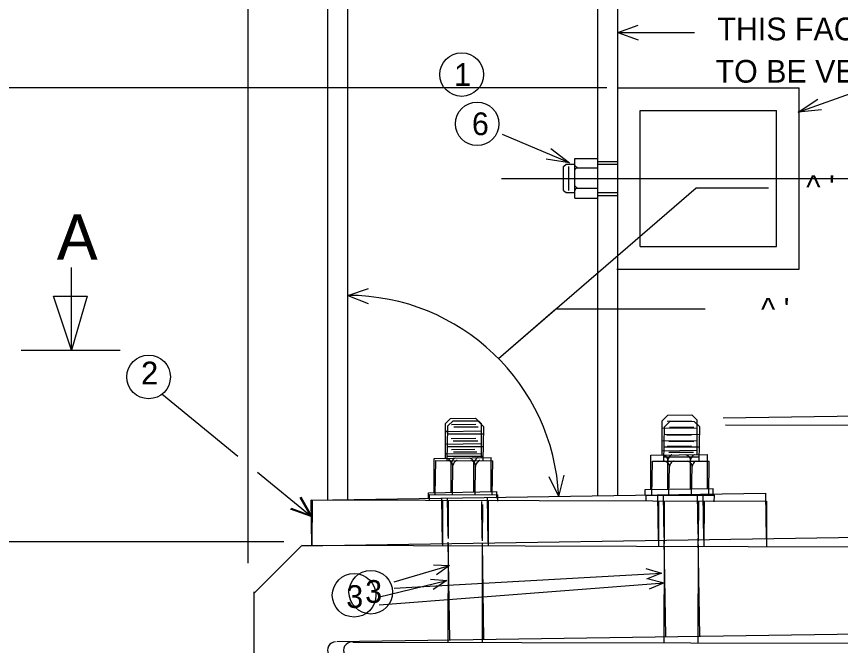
# Model space of a CAD drawing. Extents: x 1509.2 to 1521.3, y 1506 to 1514.6.
# Drawn here: x 1510.447 to 1511.957, y 1509.914 to 1511.069 of the extents above; entities that cross this region are included whole.
import ezdxf

# ---------------------------------------------------------------- set-up
doc = ezdxf.new("R2010")
doc.units = 0
doc.layers.add('Level 3', color=7, linetype='Continuous')
doc.layers.add('Level 4', color=7, linetype='Continuous')

msp = doc.modelspace()

# ---------------------------------------------------------------- linework, layer by layer
at = {"layer": 'Level 3'}
for p, q in [((1511.5127, 1510.1884), (1511.5127, 1512.8863)), ((1511.5491, 1510.1896), (1511.5491, 1512.8862)), ((1511.0178, 1510.1816), (1511.0178, 1512.8483)), ((1511.0543, 1510.1816), (1511.0543, 1512.8483)), ((1510.8717, 1510.0655), (1510.8717, 1511.5101)), ((1511.5491, 1511.0391), (1511.5867, 1511.0528)), ((1511.5491, 1511.0391), (1511.6895, 1511.0391)), ((1511.5491, 1511.0391), (1511.5867, 1511.0254)), ((1511.3302, 1510.4408), (1511.6928, 1510.7544)), ((1511.6928, 1510.7544), (1511.8253, 1510.7544)), ((1510.5477, 1510.4565), (1510.5477, 1510.6081)), ((1511.0542, 1510.5567), (1511.0921, 1510.5693)), ((1510.5477, 1510.4565), (1510.5147, 1510.5553)), ((1510.5147, 1510.5553), (1510.5763, 1510.5553)), ((1510.5763, 1510.5553), (1510.5477, 1510.4565)), ((1511.0542, 1510.5567), (1511.0914, 1510.542)), ((1510.4554, 1510.4565), (1510.6366, 1510.4565)), ((1510.8522, 1510.2615), (1510.713, 1510.3753)), ((1511.7425, 1510.3321), (1512.3049, 1510.3405)), ((1511.2332, 1510.3216), (1511.2427, 1510.3311)), ((1511.2427, 1510.3311), (1511.2884, 1510.3318)), ((1511.2991, 1510.3211), (1511.2884, 1510.3318)), ((1511.6302, 1510.3265), (1511.6407, 1510.337)), ((1511.6302, 1510.2632), (1511.6302, 1510.3265)), ((1511.6395, 1510.3262), (1511.6844, 1510.3268)), ((1511.6407, 1510.337), (1511.6848, 1510.3377)), ((1511.6949, 1510.3276), (1511.6848, 1510.3377)), ((1511.6949, 1510.2643), (1511.6949, 1510.3276)), ((1511.2332, 1510.3081), (1511.2332, 1510.3216)), ((1511.2332, 1510.2581), (1511.2332, 1510.3178)), ((1511.2445, 1510.3202), (1511.2889, 1510.3208)), ((1511.2991, 1510.3135), (1511.2991, 1510.3211)), ((1511.2991, 1510.2588), (1511.2991, 1510.3194)), ((1511.6299, 1510.313), (1511.6949, 1510.314)), ((1511.2332, 1510.307), (1511.2987, 1510.308)), ((1511.2434, 1510.2943), (1511.2889, 1510.2949)), ((1511.639, 1510.3003), (1511.6844, 1510.3009)), ((1511.2332, 1510.2838), (1511.2981, 1510.2848)), ((1511.6308, 1510.2898), (1511.6947, 1510.2908)), ((1511.6395, 1510.2802), (1511.6844, 1510.2808)), ((1511.2328, 1510.2659), (1511.2988, 1510.2669)), ((1511.2445, 1510.2742), (1511.2873, 1510.2748)), ((1511.6094, 1510.2634), (1511.7137, 1510.265)), ((1511.6094, 1510.1998), (1511.6094, 1510.2634)), ((1511.6308, 1510.2719), (1511.6948, 1510.2729)), ((1511.7137, 1510.2031), (1511.7137, 1510.265)), ((1511.2124, 1510.2575), (1511.3167, 1510.2591)), ((1511.2124, 1510.195), (1511.2124, 1510.2575)), ((1511.2438, 1510.1961), (1511.2438, 1510.248)), ((1511.2853, 1510.1961), (1511.2853, 1510.2495)), ((1511.3167, 1510.1966), (1511.3167, 1510.2591)), ((1511.6408, 1510.2009), (1511.6408, 1510.2556)), ((1511.6823, 1510.2015), (1511.6823, 1510.2545)), ((1510.9869, 1510.1513), (1510.8887, 1510.2317)), ((1511.4408, 1510.188), (1511.4233, 1510.224)), ((1511.4408, 1510.188), (1511.4233, 1510.224)), ((1511.4408, 1510.188), (1511.4506, 1510.2268)), ((1511.4408, 1510.188), (1511.4506, 1510.2268)), ((1511.5991, 1510.2008), (1511.7241, 1510.2027)), ((1511.7241, 1510.1908), (1511.7241, 1510.2027)), ((1510.9865, 1510.1812), (1511.8198, 1510.1937)), ((1511.2021, 1510.1948), (1511.3271, 1510.1968)), ((1511.2021, 1510.1848), (1511.2021, 1510.1948)), ((1511.3271, 1510.1848), (1511.3271, 1510.1968)), ((1511.5991, 1510.1908), (1511.5991, 1510.2008)), ((1511.622, 1510.1908), (1511.6233, 1510.1078)), ((1511.6323, 1510.1909), (1511.6335, 1510.1127)), ((1511.6948, 1510.1919), (1511.6959, 1510.1188)), ((1511.7053, 1510.1921), (1511.7065, 1510.1078)), ((1511.8198, 1510.1937), (1511.821, 1510.1103)), ((1510.9869, 1510.1513), (1510.9665, 1510.1857)), ((1510.9865, 1510.1812), (1510.9878, 1510.0978)), ((1510.9866, 1510.1813), (1510.9878, 1510.0979)), ((1511.2262, 1510.1848), (1511.2274, 1510.1017)), ((1511.2365, 1510.1849), (1511.2376, 1510.1151)), ((1511.2991, 1510.1786), (1511.3001, 1510.1114)), ((1511.3094, 1510.1861), (1511.3107, 1510.1041)), ((1510.9869, 1510.1513), (1510.9492, 1510.1645)), ((1510.9693, 1510.0976), (1512.445, 1510.1198)), ((1510.9368, 1510.1046), (1510.3492, 1510.1046)), ((1510.8824, 1510.0107), (1510.9693, 1510.0976)), ((1511.2378, 1510.1041), (1511.2404, 1509.9247)), ((1511.3003, 1510.1017), (1511.3029, 1509.9258)), ((1511.6336, 1510.1078), (1511.6363, 1509.9318)), ((1511.6961, 1510.1114), (1511.6988, 1509.9318)), ((1511.139, 1510.0313), (1511.2408, 1510.0613)), ((1511.139, 1510.0197), (1511.6293, 1510.0474)), ((1510.8824, 1509.5244), (1510.8824, 1510.013)), ((1511.0337, 1509.9216), (1512.4477, 1509.9428))]:
    msp.add_line(p, q, dxfattribs=at)
for points in [[(1511.211, 1510.0627), (1511.2408, 1510.0613), (1511.2165, 1510.044)], [(1511.6007, 1510.0556), (1511.6293, 1510.0474), (1511.6018, 1510.0361)]]:
    msp.add_lwpolyline(points, dxfattribs=at)
for centre in [(1511.2629, 1510.962), (1510.6889, 1510.4072), (1511.0963, 1510.0122)]:
    msp.add_circle(centre, 0.04, dxfattribs=at)
for centre, radius, start, end in [((1511.0541, 1510.1697), 0.3871, 2.7146, 89.9796), ((1511.0318, 1509.9062), 0.0148, 90.3237, 271.1515)]:
    msp.add_arc(centre, radius, start, end, dxfattribs=at)
for centre, major_axis, ratio, start_param, end_param in [((1511.6303, 1510.2571), (0.0104, -0.0031), 0.648879, 0, 1.570796), ((1511.6446, 1510.259), (-0.00363, -0.00504), 0.295973, 3.141593, 6.283185), ((1511.6719, 1510.2577), (0.0104, -0.0031), 0.648879, 0, 1.570796), ((1511.6862, 1510.2595), (-0.00363, -0.00504), 0.295973, 3.141593, 6.283185), ((1511.2332, 1510.2511), (0.0104, -0.0031), 0.648879, 0, 1.570796), ((1511.2476, 1510.2531), (-0.00363, -0.00504), 0.295973, 3.141593, 6.283185), ((1511.2748, 1510.2517), (0.0104, -0.0031), 0.648879, 0, 1.570796), ((1511.2892, 1510.2537), (-0.00363, -0.00504), 0.295973, 3.141593, 6.283185)]:
    msp.add_ellipse(centre, major_axis=major_axis, ratio=ratio, start_param=start_param, end_param=end_param, dxfattribs=at)
at = {"layer": 'Level 4'}
for p, q in [((1511.5127, 1510.1884), (1511.5127, 1513.6046)), ((1511.5491, 1510.1896), (1511.5491, 1513.6046)), ((1511.0178, 1510.1816), (1511.0178, 1513.5667)), ((1511.0543, 1510.1816), (1511.0543, 1513.5695)), ((1510.8717, 1510.9678), (1510.8717, 1511.7411)), ((1511.8799, 1510.8929), (1512.042, 1510.9512)), ((1511.529, 1510.9379), (1510.3492, 1510.9379)), ((1511.5491, 1510.9379), (1511.8817, 1510.9379)), ((1511.8817, 1510.6047), (1511.8817, 1510.9379)), ((1510.8717, 1510.0655), (1510.8717, 1510.9054)), ((1511.5901, 1510.8963), (1511.84, 1510.8963)), ((1511.5901, 1510.6464), (1511.5901, 1510.8963)), ((1511.84, 1510.6464), (1511.84, 1510.8963)), ((1511.4604, 1510.8003), (1511.3378, 1510.8523)), ((1511.4703, 1510.735), (1511.4703, 1510.8081)), ((1511.4703, 1510.808), (1511.5116, 1510.808)), ((1511.4494, 1510.793), (1511.4542, 1510.7974)), ((1511.4494, 1510.7495), (1511.4494, 1510.793)), ((1511.4542, 1510.7974), (1511.4703, 1510.7974)), ((1511.4596, 1510.7495), (1511.4596, 1510.793)), ((1511.5121, 1510.8027), (1511.5488, 1510.8027)), ((1511.5121, 1510.7974), (1511.5488, 1510.7974)), ((1511.4755, 1510.7911), (1511.5116, 1510.7911)), ((1511.3357, 1510.7714), (1511.9883, 1510.7714)), ((1511.4494, 1510.7495), (1511.4544, 1510.7454)), ((1511.4755, 1510.7537), (1511.5121, 1510.7537)), ((1511.4544, 1510.7454), (1511.4698, 1510.7454)), ((1511.4703, 1510.735), (1511.5121, 1510.735)), ((1511.5121, 1510.7454), (1511.5488, 1510.7454)), ((1511.5121, 1510.7403), (1511.5488, 1510.7403)), ((1511.5901, 1510.6464), (1511.84, 1510.6464)), ((1510.5477, 1510.4565), (1510.5477, 1510.6081)), ((1511.5475, 1510.6047), (1511.8817, 1510.6047)), ((1511.0542, 1510.5567), (1511.0921, 1510.5693)), ((1510.5477, 1510.4565), (1510.5147, 1510.5553)), ((1510.5147, 1510.5553), (1510.5763, 1510.5553)), ((1510.5763, 1510.5553), (1510.5477, 1510.4565)), ((1511.0542, 1510.5567), (1511.0914, 1510.542)), ((1511.3302, 1510.4408), (1511.4357, 1510.532)), ((1511.4357, 1510.532), (1511.709, 1510.532)), ((1510.4554, 1510.4565), (1510.6366, 1510.4565)), ((1510.8522, 1510.2615), (1510.713, 1510.3753)), ((1511.2375, 1510.3176), (1511.2471, 1510.3268)), ((1511.2471, 1510.3268), (1511.2928, 1510.3267)), ((1511.3033, 1510.3159), (1511.2928, 1510.3267)), ((1511.6345, 1510.3154), (1511.6452, 1510.3258)), ((1511.6452, 1510.3258), (1511.6893, 1510.3257)), ((1511.6993, 1510.3154), (1511.6893, 1510.3257)), ((1511.2363, 1510.2541), (1511.2373, 1510.3138)), ((1511.2372, 1510.3041), (1511.2375, 1510.3176)), ((1511.2488, 1510.3159), (1511.2932, 1510.3158)), ((1511.3023, 1510.2536), (1511.3033, 1510.3143)), ((1511.3033, 1510.3083), (1511.3033, 1510.3159)), ((1511.6333, 1510.2522), (1511.6345, 1510.3154)), ((1511.6438, 1510.3149), (1511.6887, 1510.3149)), ((1511.6981, 1510.2522), (1511.6993, 1510.3154)), ((1511.7468, 1510.3191), (1512.3093, 1510.3178)), ((1511.2371, 1510.303), (1511.3026, 1510.3028)), ((1511.6339, 1510.3019), (1511.6989, 1510.3018)), ((1511.2368, 1510.2798), (1511.3018, 1510.2797)), ((1511.2473, 1510.29), (1511.2928, 1510.2898)), ((1511.6344, 1510.2788), (1511.6983, 1510.2787)), ((1511.6428, 1510.2891), (1511.6883, 1510.289)), ((1511.248, 1510.2699), (1511.2908, 1510.2698)), ((1511.6429, 1510.269), (1511.6879, 1510.2689)), ((1511.2145, 1510.1913), (1511.2155, 1510.2538)), ((1511.2155, 1510.2538), (1511.3198, 1510.2535)), ((1511.2361, 1510.2619), (1511.3021, 1510.2617)), ((1511.3188, 1510.191), (1511.3198, 1510.2535)), ((1511.6115, 1510.1893), (1511.6126, 1510.2528)), ((1511.6126, 1510.2528), (1511.7168, 1510.2526)), ((1511.6342, 1510.2608), (1511.6982, 1510.2608)), ((1511.7158, 1510.1907), (1511.7168, 1510.2526)), ((1511.2458, 1510.1918), (1511.2468, 1510.2438)), ((1511.2874, 1510.1912), (1511.2883, 1510.2445)), ((1511.6428, 1510.1898), (1511.6438, 1510.2443)), ((1511.6844, 1510.1896), (1511.6853, 1510.2427)), ((1510.9869, 1510.1513), (1510.8887, 1510.2317)), ((1511.4408, 1510.188), (1511.4233, 1510.224)), ((1511.4408, 1510.188), (1511.4233, 1510.224)), ((1511.4408, 1510.188), (1511.4506, 1510.2268)), ((1511.4408, 1510.188), (1511.4506, 1510.2268)), ((1511.204, 1510.1813), (1511.2042, 1510.1913)), ((1511.2042, 1510.1913), (1511.3292, 1510.191)), ((1511.3289, 1510.1791), (1511.3292, 1510.191)), ((1511.601, 1510.1804), (1511.6012, 1510.1903)), ((1511.6012, 1510.1903), (1511.7262, 1510.1901)), ((1511.7259, 1510.1783), (1511.7262, 1510.1901)), ((1510.9883, 1510.1515), (1510.9684, 1510.1863)), ((1510.9884, 1510.1815), (1510.9881, 1510.098)), ((1510.9885, 1510.1816), (1510.9882, 1510.0981)), ((1510.9884, 1510.1815), (1511.8217, 1510.1794)), ((1511.228, 1510.1809), (1511.2279, 1510.0978)), ((1511.2383, 1510.1808), (1511.2382, 1510.111)), ((1511.3008, 1510.1733), (1511.3007, 1510.1062)), ((1511.3113, 1510.1807), (1511.3112, 1510.0987)), ((1511.6239, 1510.18), (1511.6237, 1510.0969)), ((1511.6343, 1510.1798), (1511.634, 1510.1016)), ((1511.6968, 1510.1798), (1511.6966, 1510.1067)), ((1511.7072, 1510.1798), (1511.707, 1510.0955)), ((1511.8217, 1510.1794), (1511.8215, 1510.0961)), ((1510.9883, 1510.1515), (1510.9507, 1510.1655)), ((1510.9368, 1510.1046), (1510.3492, 1510.1046)), ((1510.8824, 1510.0107), (1510.9693, 1510.0976)), ((1510.9697, 1510.0983), (1512.4456, 1510.0946)), ((1511.2382, 1510.1), (1511.2377, 1509.9205)), ((1511.6966, 1510.0993), (1511.6961, 1509.9197)), ((1511.3007, 1510.0964), (1511.3003, 1509.9205)), ((1511.6341, 1510.0967), (1511.6336, 1509.9208)), ((1511.1096, 1510.0033), (1511.2357, 1510.0334)), ((1511.1116, 1509.9893), (1511.6341, 1510.0294)), ((1510.8824, 1509.5244), (1510.8824, 1510.013)), ((1511.0634, 1509.9207), (1512.4419, 1509.9173))]:
    msp.add_line(p, q, dxfattribs=at)
for points in [[(1511.9227, 1510.8972), (1511.8799, 1510.8929), (1511.9156, 1510.9168)], [(1511.4262, 1510.8262), (1511.4604, 1510.8003), (1511.418, 1510.807)], [(1511.206, 1510.0363), (1511.2357, 1510.0334), (1511.2105, 1510.0174)], [(1511.6053, 1510.037), (1511.6341, 1510.0294), (1511.6068, 1510.0176)], [(1511.6053, 1510.037), (1511.6341, 1510.0294), (1511.6068, 1510.0176)]]:
    msp.add_lwpolyline(points, dxfattribs=at)
for centre in [(1511.2913, 1510.8716), (1510.6889, 1510.4072), (1511.0657, 1510.0066)]:
    msp.add_circle(centre, 0.04, dxfattribs=at)
for centre, radius, start, end in [((1511.4794, 1510.8014), 0.011, 213.851, 249.2744), ((1511.4779, 1510.7828), 0.00865, 106.0183, 151.9637), ((1511.4794, 1510.764), 0.011, 213.851, 249.2744), ((1511.4779, 1510.7453), 0.00865, 106.0183, 151.9637), ((1511.0541, 1510.1697), 0.3871, 2.7146, 89.9796), ((1511.0617, 1509.9053), 0.0156, 88.8702, 269.1445)]:
    msp.add_arc(centre, radius, start, end, dxfattribs=at)
for centre, major_axis, ratio, start_param, end_param in [((1511.2362, 1510.247), (0.0104, -0.0033), 0.648879, 0, 1.570796), ((1511.2507, 1510.2488), (-0.00371, -0.00498), 0.295973, 3.141593, 6.283185), ((1511.2778, 1510.2469), (0.0104, -0.0033), 0.648879, 0, 1.570796), ((1511.2923, 1510.2487), (-0.00371, -0.00498), 0.295973, 3.141593, 6.283185), ((1511.6333, 1510.2461), (0.0104, -0.0033), 0.648879, 0, 1.570796), ((1511.6477, 1510.2477), (-0.00371, -0.00498), 0.295973, 3.141593, 6.283185), ((1511.675, 1510.2459), (0.0104, -0.0033), 0.648879, 0, 1.570796), ((1511.6893, 1510.2476), (-0.00371, -0.00498), 0.295973, 3.141593, 6.283185)]:
    msp.add_ellipse(centre, major_axis=major_axis, ratio=ratio, start_param=start_param, end_param=end_param, dxfattribs=at)

# ---------------------------------------------------------------- texts
at = {"layer": 'Level 3'}
for s, height, p in [('THIS FACE', 0.04167, (1511.7316, 1511.0248)), ('TO BE VERT.', 0.041667, (1511.7283, 1510.9471)), ('1', 0.0417, (1511.2491, 1510.9412)), ('A', 0.0833, (1510.5205, 1510.6222)), ('2', 0.0417, (1510.6751, 1510.3935)), ('3', 0.0417, (1511.086, 1509.9927))]:
    msp.add_text(s, height=height, rotation=0, dxfattribs=at).set_placement(p)
msp.add_text("  ^  '", height=0.04167, dxfattribs=at).set_placement((1511.8637, 1510.7353))
at = {"layer": 'Level 4'}
for s, height, p in [('6', 0.0417, (1511.2817, 1510.8508)), ('A', 0.0833, (1510.5213, 1510.6222)), ('2', 0.0417, (1510.6755, 1510.3935)), ('3', 0.0417, (1511.0513, 1509.9834))]:
    msp.add_text(s, height=height, rotation=0, dxfattribs=at).set_placement(p)
msp.add_text("  ^  '", height=0.04167, dxfattribs=at).set_placement((1511.7807, 1510.5106))

doc.saveas('drawing.dxf')
